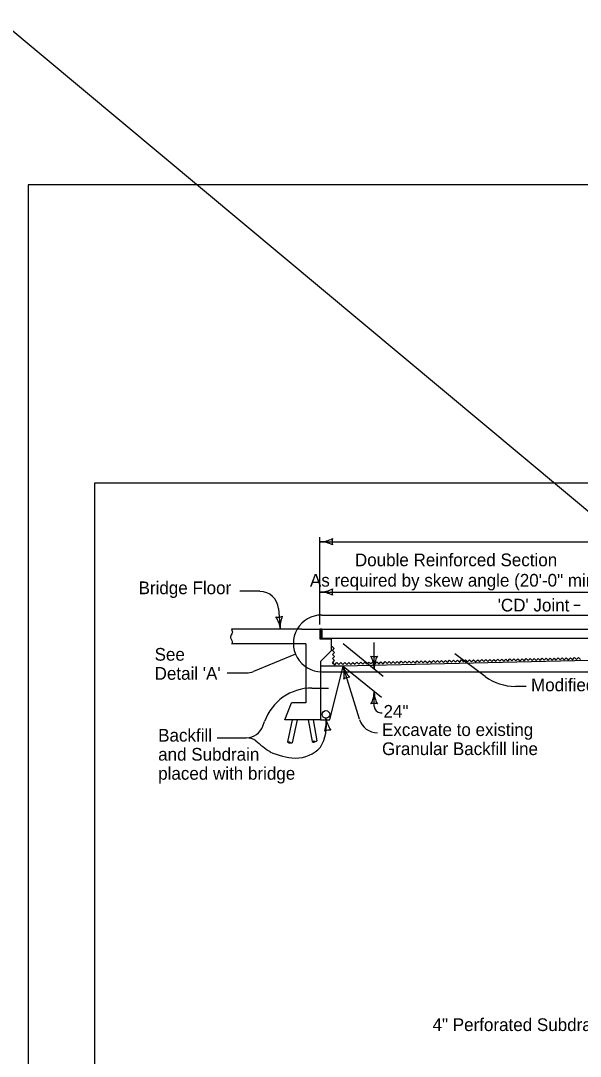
# Model space of a CAD drawing. Extents: x 8925 to 81668, y 4369 to 11918.
# Drawn here: x 13587 to 14467, y 5831 to 7462 of the extents above; entities that cross this region are included whole.
import ezdxf

# ---------------------------------------------------------------- set-up
doc = ezdxf.new("R2010")
doc.units = 0
for name, color, linetype in [('dsnShtPlotShapeBatchPrint', 7, 'Continuous'), ('dsnStdBlock', 7, 'Continuous'), ('dsnStdBlockNotModified', 7, 'Continuous'), ('dsnStdBorder', 7, 'Continuous'), ('Level 3', 7, 'Continuous'), ('SheetBorder', 7, 'Continuous')]:
    doc.layers.add(name, color=color, linetype=linetype)

msp = doc.modelspace()

# ---------------------------------------------------------------- linework, layer by layer
at = {"layer": 'dsnShtPlotShapeBatchPrint'}
for p, q in [((14057, 6511.1), (14057, 6648.7)), ((14057, 6641.3), (15396.4, 6641.3)), ((14057, 6562.1), (14505.4, 6562.1)), ((14456.2, 6541.6), (14466.5, 6541.6)), ((13991.8, 6536.1), (13994.6, 6503.6)), ((14059.9, 6525.9), (14863.1, 6525.9)), ((14059.9, 6488.7), (14059.9, 6503.6)), ((14059.9, 6503.6), (14505.4, 6503.6)), ((14074.8, 6488.7), (14059.9, 6488.7)), ((14097.1, 6488.8), (14074.8, 6488.7)), ((14093.6, 6481), (14156.4, 6429.9)), ((14505.4, 6488.8), (14097.1, 6488.8)), ((14142.4, 6441.3), (14142.4, 6482.5)), ((14018.8, 6464.3), (13952.6, 6437)), ((14317.2, 6429.3), (14269.2, 6464.9)), ((14093.6, 6445.7), (14153.9, 6396.6)), ((14119.2, 6361.8), (14093.6, 6445.7)), ((13941.2, 6434.7), (13911.2, 6434.7)), ((14059.9, 6436.8), (14863.1, 6436.8)), ((14044.6, 6411.1), (14070.4, 6411.1)), ((14381.3, 6413.7), (14364.4, 6413.7)), ((14142.4, 6382.1), (14142.4, 6406)), ((14152.4, 6372.1), (14154.8, 6372.1)), ((13967.4, 6351), (13970.1, 6358.6)), ((13895.5, 6332.7), (13941.3, 6332.7))]:
    msp.add_line(p, q, dxfattribs=at)
for centre, radius, start, end in [((14059.9, 6481.4), 44.6, 89.9996, 270), ((13941.2, 6464.5), 29.7, 270, 292.4496), ((14364.4, 6492.9), 79.2, 233.4243, 270), ((13996, 6353), 71.3, 330.5092, 8.5915), ((14147.6, 6370.4), 29.7, 196.9535, 270), ((14067.7, 6448.1), 163.6, 227.1442, 236.9942), ((14027.5, 6418.7), 118.5, 245.5915, 265.546), ((14018, 6355.6), 55, 270.3325, 316.7198)]:
    msp.add_arc(centre, radius, start, end, dxfattribs=at)
at = {"layer": 'dsnStdBlock'}
msp.add_lwpolyline([(13703, 6733.9), (16838, 6733.9), (16838, 4723.9), (13703, 4723.9)], close=True, dxfattribs=at)
at = {"layer": 'dsnStdBlockNotModified'}
msp.add_lwpolyline([(13598.5, 4619.4), (16942.5, 4619.4), (16942.5, 7203.4), (13598.5, 7203.4)], close=True, dxfattribs=at)
at = {"layer": 'dsnStdBorder'}
for p, q in [((13962.7, 6563.3), (13930.9, 6563.3)), ((14028.7, 6503.6), (13918.1, 6503.6)), ((14028.7, 6503.6), (14057, 6503.6)), ((14057, 6503.6), (14057, 6488.7)), ((14059.9, 6503.6), (14057, 6503.6)), ((14057, 6502.4), (14057.8, 6503.2)), ((14057, 6500.3), (14059.9, 6503.2)), ((14059.9, 6503.2), (14057, 6503.2)), ((14057, 6498.2), (14059.9, 6501.1)), ((14057, 6496.1), (14059.9, 6499)), ((14057, 6494), (14059.9, 6496.9)), ((14057, 6491.9), (14059.9, 6494.8)), ((14057, 6489.8), (14059.9, 6492.7)), ((14058, 6488.7), (14059.9, 6490.6)), ((14059.9, 6503.6), (14059.9, 6488.7)), ((14059.9, 6503.6), (15214.8, 6503.6)), ((14034.7, 6480.7), (13918.1, 6480.7)), ((14034.7, 6480.7), (14034.7, 6387.8)), ((14057, 6488.7), (14074.8, 6488.7)), ((15201.2, 6488.8), (14059.9, 6488.8)), ((14097.1, 6488.8), (14073.8, 6488.7)), ((14074.8, 6488.7), (14074.8, 6469.5)), ((14074.8, 6469.5), (14058, 6452.7)), ((15210.8, 6471), (14093.6, 6445.7)), ((14058, 6452.7), (14058, 6361.1)), ((14093.6, 6445.7), (14058, 6445.7)), ((14072.9, 6361.1), (14093.6, 6445.7)), ((14002, 6361.1), (14012.3, 6387.8)), ((14034.7, 6387.8), (14012.3, 6387.8)), ((14058, 6361.1), (14002, 6361.1)), ((14013.5, 6361.1), (14006, 6326.3)), ((14021.1, 6361.1), (14013.2, 6324.7)), ((14038.7, 6361.1), (14045, 6326.7)), ((14046.3, 6361.1), (14052.4, 6328.1)), ((14058, 6361.1), (14072.9, 6361.1))]:
    msp.add_line(p, q, dxfattribs=at)
for points in [[(14078.7, 6449.3), (14077, 6450.9), (14080.1, 6454.2), (14076.9, 6457.3), (14079.9, 6460.5), (14076.7, 6463.6), (14079.8, 6466.9), (14076.6, 6469.9), (14079.6, 6473.2), (14076.4, 6476.3), (14076.6, 6476.4)], [(14287.8, 6453.7), (14289.4, 6452.2), (14292.5, 6455.4), (14295.7, 6452.3), (14298.8, 6455.6), (14302.1, 6452.5), (14305.2, 6455.7), (14308.4, 6452.6), (14311.5, 6455.8), (14314.7, 6452.7), (14317.8, 6456), (14321.1, 6452.9), (14324.2, 6456.1), (14327.4, 6453), (14330.5, 6456.2), (14333.7, 6453.1), (14336.8, 6456.4), (14340.1, 6453.3), (14343.2, 6456.5), (14346.4, 6453.4), (14349.5, 6456.7), (14352.7, 6453.6), (14355.9, 6456.8), (14359.1, 6453.7), (14362.2, 6456.9), (14363.8, 6455.4)], [(14363.8, 6455.4), (14365.4, 6453.8), (14368.5, 6457.1), (14371.8, 6454), (14374.9, 6457.2), (14378.1, 6454.1), (14381.2, 6457.3), (14384.4, 6454.2), (14387.5, 6457.5), (14390.8, 6454.4), (14393.9, 6457.6), (14397.1, 6454.5), (14400.2, 6457.7), (14403.4, 6454.6), (14406.5, 6457.9), (14409.8, 6454.8), (14412.9, 6458), (14416.1, 6454.9), (14419.2, 6458.1), (14422.4, 6455), (14425.5, 6458.3), (14428.8, 6455.2), (14431.9, 6458.4), (14435.1, 6455.3), (14438.2, 6458.5), (14439.8, 6457)], [(14439.8, 6457), (14441.4, 6455.5), (14444.5, 6458.7), (14447.8, 6455.6), (14450.9, 6458.8), (14454.1, 6455.7), (14457.2, 6459), (14460.4, 6455.9), (14463.5, 6459.1), (14466.8, 6456)], [(14077.1, 6450.8), (14077.1, 6450.8), (14080.4, 6447.7), (14083.5, 6451), (14086.7, 6447.9), (14089.8, 6451.1), (14093, 6448), (14096.1, 6451.2), (14099.4, 6448.1), (14102.5, 6451.4), (14105.7, 6448.3), (14108.8, 6451.5), (14112, 6448.4), (14115.1, 6451.6), (14118.4, 6448.5), (14121.5, 6451.8), (14124.7, 6448.7), (14127.8, 6451.9), (14131, 6448.8), (14134.1, 6452), (14135.8, 6450.5)], [(14135.8, 6450.5), (14137.4, 6448.9), (14140.5, 6452.2), (14143.7, 6449.1), (14146.8, 6452.3), (14150, 6449.2), (14153.1, 6452.4), (14156.4, 6449.4), (14159.5, 6452.6), (14162.7, 6449.5), (14165.8, 6452.7), (14169.1, 6449.6), (14172.1, 6452.9), (14175.4, 6449.8), (14178.5, 6453), (14181.7, 6449.9), (14184.8, 6453.1), (14188.1, 6450), (14191.2, 6453.3), (14194.4, 6450.2), (14197.5, 6453.4), (14200.7, 6450.3), (14203.8, 6453.5), (14207.1, 6450.4), (14210.2, 6453.7), (14211.8, 6452.1)], [(14211.8, 6452.1), (14213.4, 6450.6), (14216.5, 6453.8), (14219.7, 6450.7), (14222.8, 6453.9), (14226.1, 6450.8), (14229.2, 6454.1), (14232.4, 6451), (14235.5, 6454.2), (14238.7, 6451.1), (14241.8, 6454.4), (14245.1, 6451.3), (14248.2, 6454.5), (14251.4, 6451.4), (14254.5, 6454.6), (14257.7, 6451.5), (14260.8, 6454.8), (14264.1, 6451.7), (14267.2, 6454.9), (14270.4, 6451.8), (14273.5, 6455), (14276.7, 6451.9), (14279.8, 6455.2), (14283.1, 6452.1), (14286.2, 6455.3), (14287.8, 6453.7)]]:
    msp.add_lwpolyline(points, dxfattribs=at)
msp.add_circle((14066.5, 6369.6), 5.94, dxfattribs=at)
for centre, radius, start, end in [((13962.2, 6533.6), 29.7, 4.9696, 89.1065), ((14142.4, 6477.1), 16.5, 252.2666, 287.7333), ((14099.6, 6441.3), 42.7, 360, 28.0725), ((14142.4, 6477.1), 16.5, 252.2666, 287.7333), ((14099.6, 6441.3), 42.7, 360, 28.0725), ((14185.1, 6441.3), 42.7, 151.9275, 180), ((14185.1, 6441.3), 42.7, 151.9275, 180), ((14044.6, 6331.9), 79.2, 90, 160.3012), ((14152.4, 6382.1), 10, 180, 270), ((13941.3, 6360.4), 27.7, 270, 340.3019), ((13941.3, 6304.9), 27.7, 56.8248, 90)]:
    msp.add_arc(centre, radius, start, end, dxfattribs=at)
for points in [[(13918.1, 6503.6), (13919.3, 6497.7), (13916.3, 6491.7), (13919.1, 6484), (13918.6, 6480.7)], [(14006, 6326.3), (14009.1, 6326.6), (14010.8, 6324.9), (14013.2, 6324.7)], [(14006, 6326.3), (14008.1, 6324.8), (14010.5, 6325)], [(14045, 6326.7), (14047.8, 6327.9), (14050.6, 6326.7), (14052.4, 6328.1)], [(14045, 6326.7), (14047.8, 6325.8), (14049.8, 6326.7)]]:
    msp.add_spline(points, degree=3, dxfattribs=at)
at = {"layer": 'Level 3'}
for centre, radius, start, end in [((14057, 6683.8), 42.5, 270, 298.0725), ((14057, 6598.8), 42.5, 61.9275, 90), ((14092.6, 6641.3), 16.4, 162.2666, 197.7334), ((14057, 6604.6), 42.5, 270, 298.0725), ((14057, 6519.6), 42.5, 61.9275, 90), ((14092.6, 6562.1), 16.4, 162.2666, 197.7334), ((13991.5, 6539.1), 16.4, 257.2333, 292.7), ((13952.3, 6500), 42.5, 4.9667, 33.0392), ((14037, 6507.3), 42.5, 156.8942, 184.9667), ((14134.2, 6458.1), 42.5, 196.9516, 225.0241), ((14052.9, 6433.3), 42.5, 348.8791, 16.9516), ((14104, 6411.6), 16.4, 89.2182, 124.6849), ((14099.9, 6406), 42.5, 331.9275, 360), ((14184.9, 6406), 42.5, 180, 208.0725), ((14142.4, 6370.3), 16.4, 72.2666, 107.7334), ((14024.5, 6357.3), 42.5, 340.519, 8.5915), ((14108.5, 6370), 42.5, 188.5915, 216.6639), ((14071.8, 6328.4), 16.4, 80.8581, 116.3248)]:
    msp.add_arc(centre, radius, start, end, dxfattribs=at)
at = {"layer": 'SheetBorder'}
msp.add_line((13555.2, 7461.7), (17208.8, 4407.7), dxfattribs=at)

# ---------------------------------------------------------------- texts
at = {"layer": 'dsnShtPlotShapeBatchPrint'}
for s, p in [('Double Reinforced Section', (14112.1, 6602.8)), ('As required by skew angle (20\'-0" min.)', (14041.4, 6570.7)), ('Bridge Floor', (13771.9, 6558.8)), ("'CD' Joint", (14336.6, 6531.6)), ('See', (13797.1, 6454.1)), ("Detail 'A'", (13797.1, 6424.1)), ('Modified Subbase', (14389.1, 6406)), ('24"', (14157.1, 6364.4)), ('Backfill', (13802.7, 6326.7)), ('Excavate to existing', (14154.7, 6335.5)), ('Granular Backfill line', (14154.7, 6305.5)), ('and Subdrain', (13802.7, 6296.7)), ('placed with bridge', (13802.7, 6266.7)), ('4" Perforated Subdrain', (14234.2, 5871))]:
    msp.add_text(s, height=20, dxfattribs=at).set_placement(p)

doc.saveas('drawing.dxf')
